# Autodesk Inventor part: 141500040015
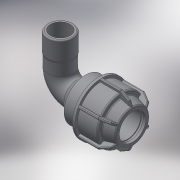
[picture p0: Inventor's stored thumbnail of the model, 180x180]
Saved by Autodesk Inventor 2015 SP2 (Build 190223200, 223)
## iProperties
Created: 2017-08
Part Number: 141500040015
Material: Generic
Description: L.14 90° ELBOW FEMALE ADAPTOR (SILVER) 40-1.1/2"
Document SubType Name: Modeling
Designer: KIM
Density: 1 g/cm^3
Appearance: Default
Author: KIM
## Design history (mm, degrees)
derived "141500.ipt"
feature "Solid1::141500.ipt"
feature "Solid2::141500.ipt"
tag "TaggingFeature1"
body "Solid1"
body "Solid2"
other parameters: "d2" = 62, "d4" = 15 deg, "d5" = 40.92, "d6" = 13.5036, "d10" = 73, "d16" = 40.8, "d17" = 3.1, "d22" = 64, "d24" = 3.1, "d25" = 65.7, "d26" = 54.75, "d27" = 3.1, "d28" = 135 deg, "d29" = 1.86, "d31" = 2, "d46" = 150 deg, "d49" = 3.65, "d50" = 0, "d58" = 1.2, "d61" = 360 deg, "d63" = 36, "d95" = 44.845, "d96" = 58.2985, "d97" = 25, "d98" = 35.876, "d99" = 52.46865, "d100" = 135 deg, "d108" = 2, "d112" = 32.5, "d113" = 86, "d114" = 63.24, "d115" = 52.46865, "d116" = 45 deg, "d117" = 0, "d118" = 0, "G_" = 44.845, "E_" = 73, "A_" = 86, "l_" = 62, "l_2" = 25
